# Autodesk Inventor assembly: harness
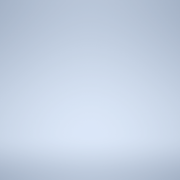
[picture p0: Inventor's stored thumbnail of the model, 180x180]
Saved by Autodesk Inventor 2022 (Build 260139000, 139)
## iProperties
Part Number: harness
Document SubType Name: Assembly
Created: 2002-07
HarnessSettings: <HarnessSettings><Defaults><Segments><Diameter value="0.200 in" fromwires="True"/><Offset value="0.100 in"/><ColorStyle value="Blue"/><BendRadius value="19" fro
Control State: 0
Master: False
Checked Out: False
Shininess: 64.0
Length Units: 11272
Angle Units: 11279
Time Units: 11290
Mass Units: 11286
Length Display Precision: 3
Angle Display Precision: 2
Compacted: True
Density: 0.0
Volumn: 0.0
Area: 0.0
PropertySet Name: Model Information
HarnessSettings: <HarnessSettings><Defaults><Segments><Diameter value="0.200 in" fromwires="True"/><Offset value="0.100 in"/><ColorStyle value="Blu - Pittura muro - Lucida"/><Ro
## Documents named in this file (1)
- C:\Users\ENU\Desktop\enu\new\harness.iam
